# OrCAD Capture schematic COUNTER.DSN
size A; company: mycompany; note: line1; note: line 2
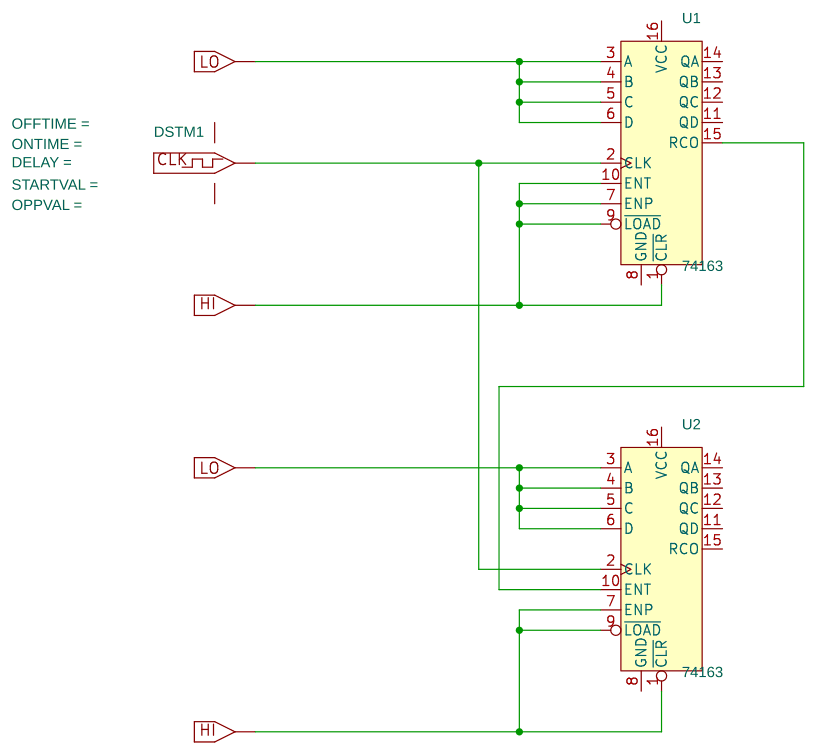
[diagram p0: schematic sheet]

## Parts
DSTM1  DigClock
U1  74163  [DIP.100/16/W.300/L.900]
U2  74163  [DIP.100/16/W.300/L.900]

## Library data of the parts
DSTM1 = DigClock
U1 U2 = 74163

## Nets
GND: DSTM1.3(GND) U1.8(GND) U2.8(GND)
VCC: DSTM1.2(VCC) U1.16(VCC) U2.16(VCC)
$D_HI: U1.1(~{CLR}) U1.7(ENP) U1.9(~{LOAD}) U1.10(ENT) U2.1(~{CLR}) U2.7(ENP) U2.9(~{LOAD})
$D_LO: U1.3(A) U1.4(B) U1.5(C) U1.6(D) U2.3(A) U2.4(B) U2.5(C) U2.6(D)
N00146: U1.15(RCO) U2.10(ENT)
N00403: DSTM1.1 U1.2(CLK) U2.2(CLK)

Not connected (* = marked no-connect by the designer): U1 11(QD) 12(QC) 13(QB) 14(QA); U2 11(QD) 12(QC) 13(QB) 14(QA) 15(RCO)
